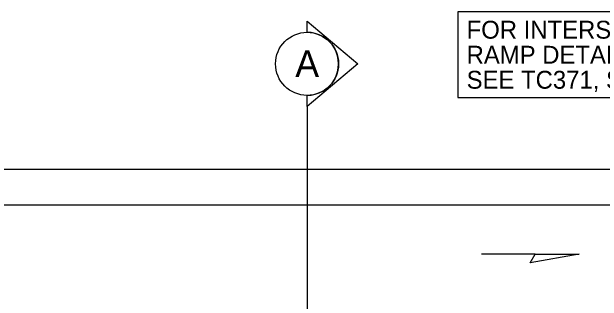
# Model space of a CAD drawing. Extents: x 99958 to 100136, y 99935 to 100013.
# Drawn here: x 100030.117 to 100032.763, y 99976.165 to 99977.46 of the extents above; entities that cross this region are included whole.
import ezdxf

# ---------------------------------------------------------------- set-up
doc = ezdxf.new("R2010")
doc.units = 0
for name, color, linetype in [('RD_ED_ShoulderPavedEdge', 7, 'Continuous'), ('RD_MK_LineEdgeYellow', 7, 'Continuous'), ('SH_TI_Tables', 7, 'Continuous'), ('SH_TI_WZSectionCut', 7, 'Continuous'), ('TR_WZ_WorkZoneDetails', 7, 'Continuous')]:
    doc.layers.add(name, color=color, linetype=linetype)

msp = doc.modelspace()

# ---------------------------------------------------------------- linework, layer by layer
at = {"layer": 'RD_ED_ShoulderPavedEdge'}
msp.add_line((100021.7753, 99976.7557), (100035.62, 99976.7557), dxfattribs=at)
at = {"layer": 'RD_MK_LineEdgeYellow'}
msp.add_line((100021.7753, 99976.5957), (100035.62, 99976.5957), dxfattribs=at)
at = {"layer": 'SH_TI_Tables'}
msp.add_lwpolyline([(100032.1152, 99977.0757), (100033.6997, 99977.0757), (100033.6997, 99977.4597), (100032.1152, 99977.4597)], close=True, dxfattribs=at)
at = {"layer": 'SH_TI_WZSectionCut'}
for p, q in [((100031.4402, 99977.3681), (100031.4402, 99977.418)), ((100031.4402, 99977.418), (100031.6684, 99977.2269)), ((100031.6684, 99977.2269), (100031.4402, 99977.0357)), ((100031.4402, 99977.0357), (100031.4402, 99977.0856)), ((100031.4402, 99977.0357), (100031.4402, 99974.9557))]:
    msp.add_line(p, q, dxfattribs=at)
msp.add_circle((100031.4402, 99977.2269), 0.1412, dxfattribs=at)
msp.add_arc((100031.4402, 99977.2269), 0.1412, 269.9978, 90.0022, dxfattribs=at)
at = {"layer": 'TR_WZ_WorkZoneDetails'}
msp.add_line((100032.4625, 99976.375), (100032.2214, 99976.375), dxfattribs=at)
msp.add_lwpolyline([(100032.6591, 99976.375), (100032.4402, 99976.3364), (100032.4625, 99976.375)], close=True, dxfattribs=at)

# ---------------------------------------------------------------- texts
at = {"layer": 'SH_TI_Tables'}
for s, p in [('FOR INTERSECTION & ', (100032.1552, 99977.3397)), ('RAMP DETAILS: ', (100032.1552, 99977.2277)), ('SEE TC371, SHEETS 2 &', (100032.1552, 99977.1157))]:
    msp.add_text(s, height=0.08, dxfattribs=at).set_placement(p)
at = {"layer": 'SH_TI_WZSectionCut'}
msp.add_text('A', height=0.12, rotation=359.99, dxfattribs=at).set_placement((100031.3873, 99977.1677))

doc.saveas('drawing.dxf')
